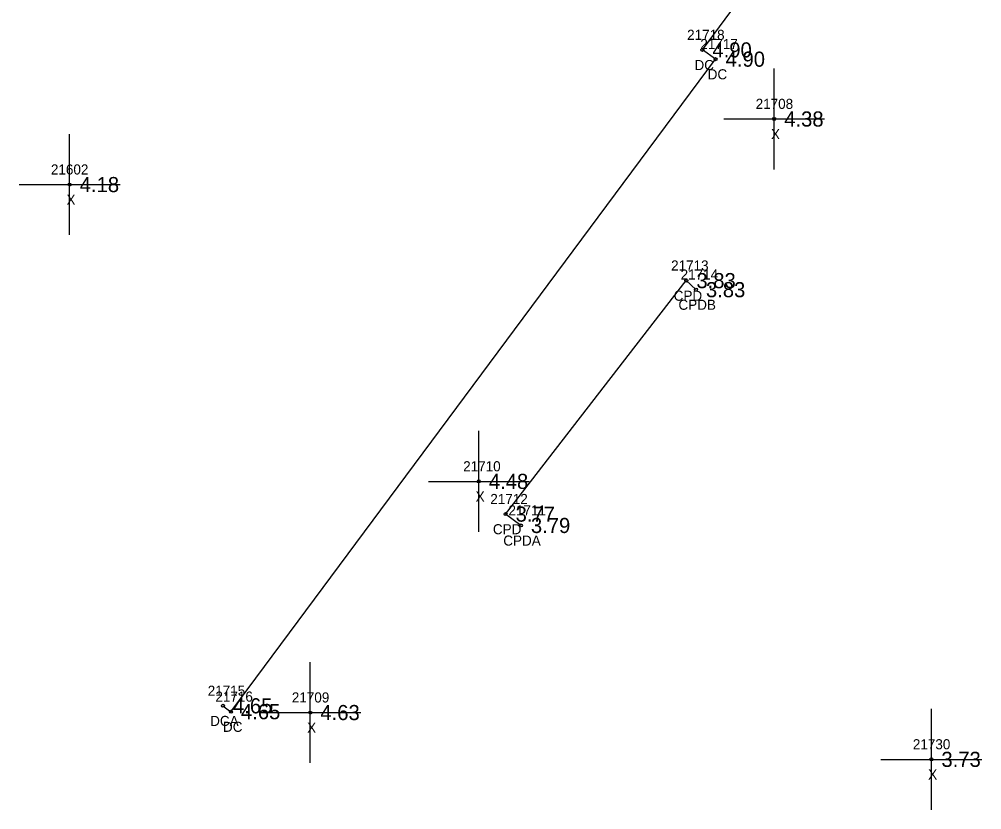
# Model space of a CAD drawing. Extents: x 2608745 to 2610333, y 641917 to 643463.
# Drawn here: x 2610077.4 to 2610172.9, y 641927.4 to 642005.8 of the extents above; entities that cross this region are included whole.
import ezdxf

# ---------------------------------------------------------------- set-up
doc = ezdxf.new("R2010")
doc.units = 0
for name, color, linetype in [('RD_EX_Conc', 7, 'Continuous'), ('RD_EX_Conc_txCode', 7, 'Continuous'), ('RD_EX_Misc', 7, 'Continuous'), ('RD_EX_Misc_txCode', 7, 'Continuous'), ('RD_EX_TX_Conc_ELEV', 7, 'Continuous'), ('RD_EX_TX_Misc_ELEV', 7, 'Continuous'), ('RD_SMD_Locator', 7, 'Continuous')]:
    doc.layers.add(name, color=color, linetype=linetype)

msp = doc.modelspace()

# ---------------------------------------------------------------- linework, layer by layer
at = {"layer": 'RD_EX_Conc'}
for points in [[(2610097.632, 641937.698), (2610098.418, 641937.114), (2610146.498, 642001.846), (2610145.188, 642002.764), (2610160.492, 642023.462), (2610172.047, 642039.304)], [(2610127.181, 641955.589), (2610125.663, 641956.716), (2610143.598, 641979.879), (2610144.544, 641978.981)]]:
    msp.add_lwpolyline(points, dxfattribs=at)
at = {"layer": 'RD_EX_Misc'}
for p, q in [((2610152.311, 641990.912), (2610152.311, 642000.912)), ((2610147.311, 641995.912), (2610157.311, 641995.912)), ((2610082.425, 641984.405), (2610082.425, 641994.405)), ((2610077.425, 641989.405), (2610087.425, 641989.405)), ((2610123.013, 641954.961), (2610123.013, 641964.961)), ((2610118.013, 641959.961), (2610128.013, 641959.961)), ((2610106.297, 641932.029), (2610106.297, 641942.029)), ((2610101.297, 641937.029), (2610111.297, 641937.029)), ((2610167.904, 641927.387), (2610167.904, 641937.387)), ((2610162.904, 641932.387), (2610172.904, 641932.387))]:
    msp.add_line(p, q, dxfattribs=at)
at = {"layer": 'RD_SMD_Locator'}
for centre in [(2610145.188, 642002.764), (2610146.498, 642001.846), (2610152.311, 641995.912), (2610082.425, 641989.405), (2610143.598, 641979.879), (2610144.544, 641978.981), (2610123.013, 641959.961), (2610125.663, 641956.716), (2610127.181, 641955.589), (2610097.632, 641937.698), (2610098.418, 641937.114), (2610106.297, 641937.029), (2610167.904, 641932.387)]:
    msp.add_circle(centre, 0.15, dxfattribs=at)

# ---------------------------------------------------------------- texts
at = {"layer": 'RD_EX_Conc_txCode'}
for s, p in [('21718', (2610143.676, 642003.764)), ('21717', (2610144.987, 642002.846)), ('DC', (2610144.408, 642000.764)), ('DC', (2610145.719, 641999.846)), ('21713', (2610142.087, 641980.879)), ('21714', (2610143.032, 641979.981)), ('CPD', (2610142.346, 641977.879)), ('CPDB', (2610142.819, 641976.981)), ('21712', (2610124.152, 641957.716)), ('21711', (2610125.953, 641956.589)), ('CPD', (2610124.412, 641954.716)), ('CPDA', (2610125.441, 641953.589)), ('21715', (2610096.12, 641938.698)), ('21716', (2610096.882, 641938.114)), ('DCA', (2610096.364, 641935.698)), ('DC', (2610097.638, 641935.114))]:
    msp.add_text(s, height=1, dxfattribs=at).set_placement(p)
at = {"layer": 'RD_EX_Misc_txCode'}
for s, p in [('21708', (2610150.477, 641996.912)), ('X', (2610151.996, 641993.912)), ('21602', (2610080.566, 641990.405)), ('X', (2610082.11, 641987.405)), ('21710', (2610121.462, 641960.961)), ('X', (2610122.698, 641957.961)), ('21709', (2610104.463, 641938.029)), ('X', (2610105.982, 641935.029)), ('21730', (2610166.07, 641933.387)), ('X', (2610167.589, 641930.387))]:
    msp.add_text(s, height=1, dxfattribs=at).set_placement(p)
at = {"layer": 'RD_EX_TX_Conc_ELEV'}
for s, p in [('4.90', (2610146.188, 642002.014)), ('4.90', (2610147.498, 642001.096)), ('3.83', (2610144.598, 641979.129)), ('3.83', (2610145.544, 641978.231)), ('3.77', (2610126.663, 641955.966)), ('3.79', (2610128.181, 641954.839)), ('4.65', (2610098.632, 641936.948)), ('4.65', (2610099.418, 641936.364))]:
    msp.add_text(s, height=1.5, dxfattribs=at).set_placement(p)
at = {"layer": 'RD_EX_TX_Misc_ELEV'}
for s, p in [('4.38', (2610153.311, 641995.162)), ('4.18', (2610083.425, 641988.655)), ('4.48', (2610124.013, 641959.211)), ('4.63', (2610107.297, 641936.279)), ('3.73', (2610168.904, 641931.637))]:
    msp.add_text(s, height=1.5, dxfattribs=at).set_placement(p)

doc.saveas('drawing.dxf')
